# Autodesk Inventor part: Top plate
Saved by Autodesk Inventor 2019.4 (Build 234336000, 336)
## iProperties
Created: 2020-04
Part Number: Top plate
Material: Generic
Document SubType Name: Modeling
Designer: Administrator
Density: 1 g/cm^3
Appearance: Default
Title: Top plate v6
Author: Administrator
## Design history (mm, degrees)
feature "Body1"
body "Solid1"
